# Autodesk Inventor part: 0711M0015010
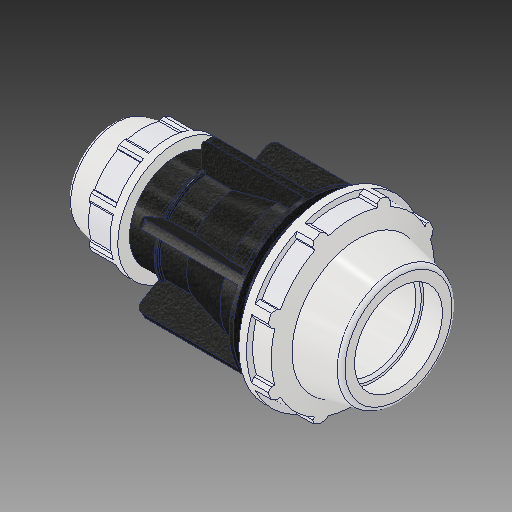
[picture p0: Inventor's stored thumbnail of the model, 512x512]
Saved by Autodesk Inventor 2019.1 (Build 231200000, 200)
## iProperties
Created: 2017-02
Part Number: 0711M0015010
Material: PVC-Piping
Description: PLASSON REDUCING COUPLER 1 1/2'' - 3/4''
Document SubType Name: Modeling
Designer: KIM
Mass: 92.6774 g
Surface Area: 199.44 cm^2
Volume: 66.1981 cm^3
Density: 1.4 g/cm^3
Appearance: PTFE
Author: KIM
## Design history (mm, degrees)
derived "0711M0.ipt"
feature "Solid1::0711M0.ipt"
tag "TaggingFeature1"
body "Solid1"
other parameters: "d_" = 48.1, "E_" = 96.012, "H_" = 156, "l_" = 64.008, "d_1" = 33.3, "E_1" = 64.008, "l_1" = 67, "d96" = 10.2942, "d2" = 48.1, "d4" = 13, "d5" = 22.28571, "d7" = 96.012, "d9" = 22.28571, "d11" = 2.22857, "d12" = 76.8096, "d13" = 120 deg, "d14" = 62.53, "d15" = 12 deg, "d16" = 86.4108, "d18" = 2.405, "d19" = 35 deg, "d20" = 17.5 deg, "d21" = 89.29116, "d23" = 0, "d25" = 360 deg, "d27" = 1.92024, "d42" = 17.16, "d46" = 1.443, "d51" = 156, "d52" = 53.7931, "d53" = 12 deg, "d54" = 64.008, "d56" = 49.95, "d57" = 33.3, "d58" = 43.29, "d59" = 29.97, "d60" = 57.6072, "d61" = 51.2064, "d62" = 15.6, "d63" = 18.72, "d64" = 120 deg, "d65" = 64.008, "d68" = 11.14286, "d74" = 59.52744, "d75" = 35 deg, "d76" = 17.5 deg, "d78" = 0, "d80" = 360 deg, "d85" = 1.28016, "d88" = 0.666, "d93" = 67, "d94" = 67.2084, "d97" = 3.4314, "d98" = 4.2672, "d99" = 0, "d100" = 3.84048, "d102" = 360 deg, "d104" = 2, "d106" = 0, "d107" = 4.2672, "d108" = 0, "d109" = 4.2672, "d110" = 0
